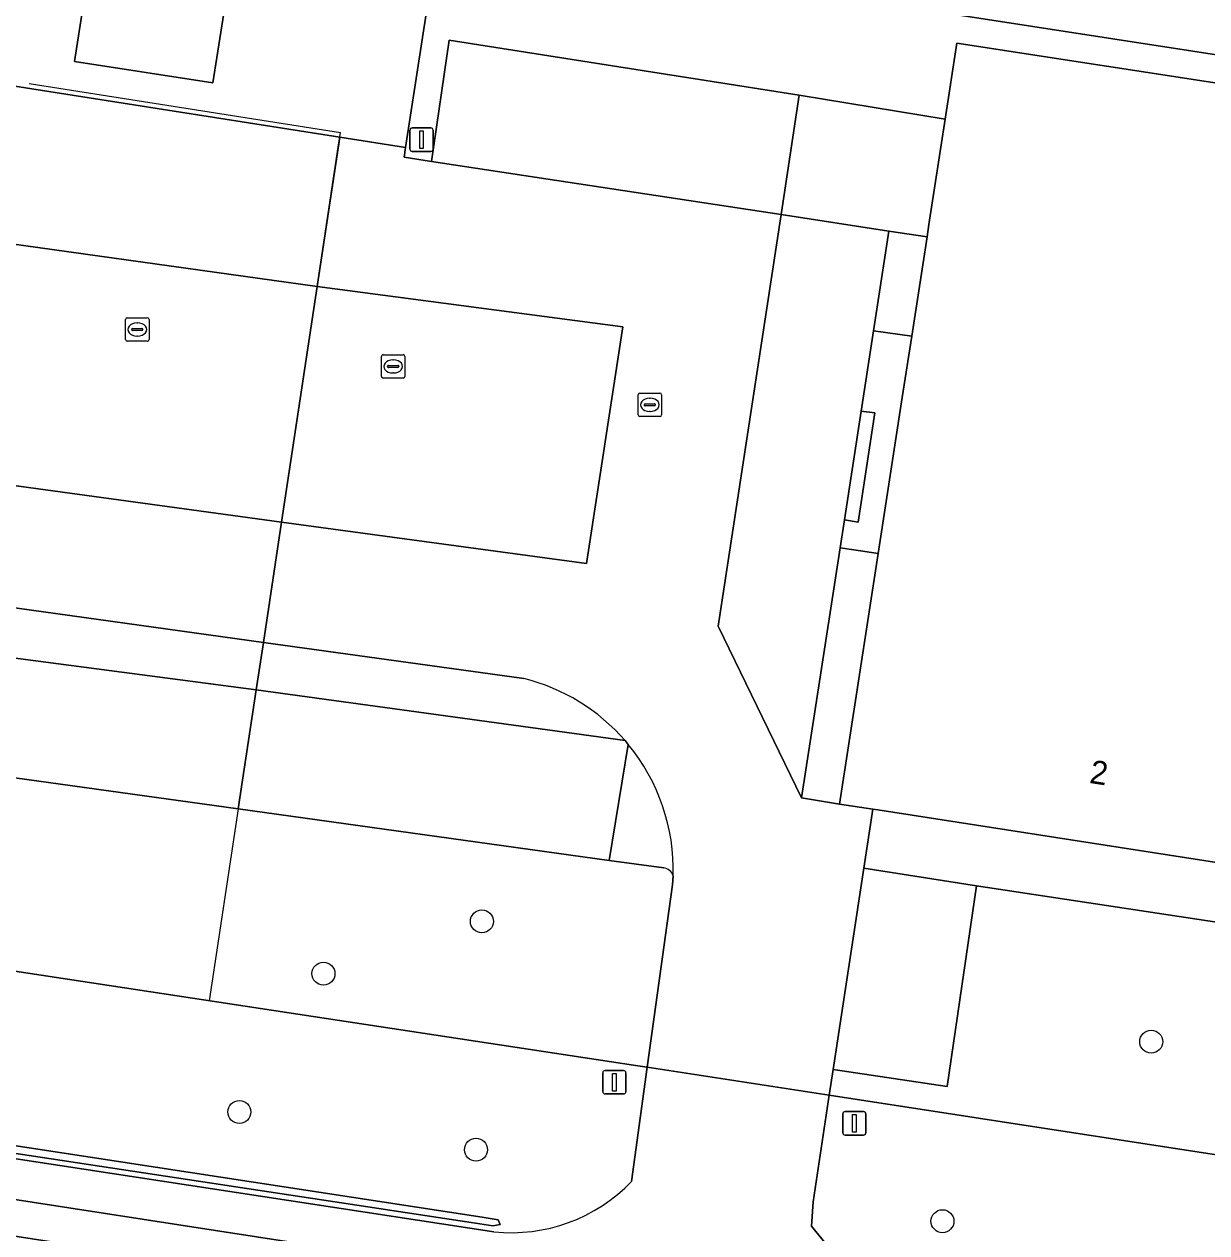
# Model space of a CAD drawing. Extents: x 161090 to 161692, y 379509 to 380907.
# Drawn here: x 161358.3 to 161408.7, y 380170.9 to 380222.4 of the extents above; entities that cross this region are included whole.
import ezdxf

# ---------------------------------------------------------------- set-up
doc = ezdxf.new("R2010")
doc.units = 0
for name, color, linetype in [('IMGEO_Boom', 7, 'Continuous'), ('IMGEO_Erf', 7, 'Continuous'), ('IMGEO_Greppel_droge_sloot', 7, 'Continuous'), ('IMGEO_Groenvoorziening', 7, 'Continuous'), ('IMGEO_Hek', 7, 'Continuous'), ('IMGEO_Kolk', 7, 'Continuous'), ('IMGEO_Lichtmast', 7, 'Continuous'), ('IMGEO_Pand', 7, 'Continuous'), ('IMGEO_Pand_nummerreeks', 7, 'Continuous'), ('IMGEO_Parkeervlak_gesloten', 7, 'Continuous'), ('IMGEO_Parkeervlak_open', 7, 'Continuous'), ('IMGEO_Rijbaan_lokaal_gesloten', 7, 'Continuous'), ('IMGEO_Rijbaan_lokaal_open', 7, 'Continuous'), ('IMGEO_Vlaggenmast', 7, 'Continuous'), ('IMGEO_Voetpad_gesloten', 7, 'Continuous'), ('IMGEO_Voetpad_open', 7, 'Continuous')]:
    doc.layers.add(name, color=color, linetype=linetype)

msp = doc.modelspace()

# ---------------------------------------------------------------- linework, layer by layer
at = {"layer": 'IMGEO_Boom'}
for centre in [(161377.798, 380184.155), (161371.038, 380181.93), (161406.356, 380179.026), (161367.451, 380176.028), (161377.548, 380174.418), (161397.449, 380171.369)]:
    msp.add_circle(centre, 0.489, dxfattribs=at)
at = {"layer": 'IMGEO_Erf'}
msp.add_lwpolyline([(161409.258, 380230.799), (161406.633, 380231.213), (161406.436, 380230.025), (161403.674, 380230.45), (161395.611, 380231.692), (161392.575, 380232.159), (161392.771, 380233.346), (161390.164, 380233.785), (161389.956, 380232.608), (161377.647, 380234.485), (161377.818, 380235.694), (161375.151, 380236.109), (161374.962, 380234.946), (161360.618, 380237.083), (161360.488, 380235.811), (161361.823, 380235.576), (161361.002, 380230.646), (161360.642, 380228.481), (161375.926, 380226.19), (161390.875, 380223.949), (161435.81, 380217.001)], dxfattribs=at)
at = {"layer": 'IMGEO_Greppel_droge_sloot'}
msp.add_lwpolyline([(161343.135, 380176.847), (161342.43, 380176.975), (161342.13, 380176.942), (161341.888, 380176.892), (161342.296, 380176.684), (161343.079, 380176.509), (161377.338, 380171.315), (161378.264, 380171.169), (161378.582, 380171.222), (161378.489, 380171.421), (161377.814, 380171.54)], close=True, dxfattribs=at)
at = {"layer": 'IMGEO_Groenvoorziening'}
for points in [[(161398.066, 380221.612), (161430.36, 380216.65), (161430.062, 380214.725), (161436.256, 380214.823), (161435.81, 380217.001), (161390.875, 380223.949), (161375.926, 380226.19), (161374.541, 380217.165), (161374.478, 380216.751), (161375.644, 380216.573), (161376.403, 380221.743), (161391.337, 380219.395), (161397.566, 380218.371)], [(161397.566, 380218.371), (161391.337, 380219.395), (161390.561, 380214.301), (161395.158, 380213.601), (161396.792, 380213.349), (161396.873, 380213.882)], [(161447.375, 380210.911), (161450.624, 380215.303), (161443.838, 380216.302), (161435.922, 380213.474), (161435.211, 380208.698), (161435.321, 380202.036), (161434.264, 380202.041), (161434.402, 380194.895), (161421.663, 380194.634), (161422.025, 380182.174), (161398.904, 380185.676), (161397.648, 380177.109), (161392.782, 380177.842), (161392.614, 380176.746), (161417.36, 380172.937), (161419.036, 380174.653), (161420.915, 380175.958), (161427.803, 380177.942), (161437.979, 380182.066), (161446.954, 380185.824), (161448.966, 380187.605), (161443.277, 380193.675)], [(161396.792, 380213.349), (161395.158, 380213.601), (161394.505, 380209.351), (161396.139, 380209.118)], [(161394.571, 380205.841), (161393.978, 380205.925), (161393.264, 380201.278), (161393.854, 380201.191)], [(161394.708, 380199.845), (161393.671, 380200.005), (161393.082, 380200.096), (161391.442, 380189.428), (161393.061, 380189.161)], [(161343.135, 380176.847), (161377.814, 380171.54), (161378.489, 380171.421), (161378.582, 380171.222), (161378.264, 380171.169), (161377.338, 380171.315), (161343.079, 380176.509), (161342.296, 380176.684), (161341.888, 380176.892), (161342.13, 380176.942), (161342.43, 380176.975)]]:
    msp.add_lwpolyline(points, close=True, dxfattribs=at)
for points in [[(161367.404, 380188.952), (161345.25, 380192.024), (161343.216, 380192.377), (161342.232, 380184.401), (161384.456, 380178.002), (161384.853, 380177.941), (161385.938, 380185.721), (161385.959, 380186.104)], [(161385.555, 380186.435), (161383.228, 380186.758), (161367.404, 380188.952)], [(161384.853, 380177.941), (161384.456, 380178.002), (161342.232, 380184.401), (161341.266, 380176.581), (161378.314, 380170.916)], [(161384.188, 380173.066), (161384.853, 380177.941)], [(161417.36, 380172.937), (161392.614, 380176.746), (161391.926, 380172.195), (161391.858, 380171.161), (161393.058, 380169.694), (161393.83, 380168.887)]]:
    msp.add_lwpolyline(points, dxfattribs=at)
for centre, radius, start, end in [((161385.52, 380185.98), 0.456, 15.7768, 85.5672), ((161379.05, 380178.004), 7.126, 264.0691, 316.1382)]:
    msp.add_arc(centre, radius, start, end, dxfattribs=at)
at = {"layer": 'IMGEO_Hek'}
for points in [[(161358.487, 380219.889), (161371.767, 380217.811)], [(161371.672, 380217.178), (161371.767, 380217.811)], [(161368.478, 380196.055), (161371.672, 380217.178)], [(161367.404, 380188.952), (161368.478, 380196.055)], [(161367.404, 380188.952), (161366.156, 380180.775)], [(161384.456, 380178.002), (161342.232, 380184.401)], [(161384.456, 380178.002), (161384.853, 380177.941)], [(161384.853, 380177.941), (161392.614, 380176.746)], [(161417.36, 380172.937), (161392.614, 380176.746)]]:
    msp.add_lwpolyline(points, dxfattribs=at)
at = {"layer": 'IMGEO_Kolk'}
for p, q in [((161362.595, 380208.976), (161362.595, 380209.828)), ((161362.67, 380209.902), (161363.522, 380209.902)), ((161363.596, 380209.828), (161363.596, 380208.976)), ((161362.854, 380209.396), (161362.854, 380209.408)), ((161363.292, 380209.359), (161362.894, 380209.359)), ((161362.897, 380209.445), (161363.295, 380209.445)), ((161363.083, 380209.682), (161363.108, 380209.682)), ((161363.338, 380209.408), (161363.338, 380209.396)), ((161363.522, 380208.902), (161362.67, 380208.902)), ((161363.106, 380209.122), (161363.081, 380209.122)), ((161373.512, 380207.402), (161373.512, 380208.254)), ((161373.587, 380208.328), (161374.439, 380208.328)), ((161374.513, 380208.254), (161374.513, 380207.402)), ((161373.771, 380207.822), (161373.771, 380207.834)), ((161374.209, 380207.785), (161373.811, 380207.785)), ((161373.814, 380207.871), (161374.212, 380207.871)), ((161374, 380208.108), (161374.025, 380208.108)), ((161374.255, 380207.834), (161374.255, 380207.822)), ((161374.439, 380207.328), (161373.587, 380207.328)), ((161374.023, 380207.548), (161373.998, 380207.548)), ((161384.54, 380206.688), (161385.392, 380206.688)), ((161384.465, 380205.762), (161384.465, 380206.614)), ((161384.724, 380206.182), (161384.724, 380206.194)), ((161384.767, 380206.231), (161385.165, 380206.231)), ((161384.953, 380206.468), (161384.978, 380206.468)), ((161385.208, 380206.194), (161385.208, 380206.182)), ((161385.466, 380206.614), (161385.466, 380205.762)), ((161385.392, 380205.688), (161384.54, 380205.688)), ((161385.162, 380206.145), (161384.764, 380206.145)), ((161384.976, 380205.908), (161384.951, 380205.908))]:
    msp.add_line(p, q, dxfattribs=at)
for points in [[(161362.595, 380208.976), (161362.595, 380209.828)], [(161362.67, 380209.902), (161363.522, 380209.902)], [(161363.596, 380209.828), (161363.596, 380208.976)], [(161363.522, 380208.902), (161362.67, 380208.902)], [(161373.512, 380207.402), (161373.512, 380208.254)], [(161373.587, 380208.328), (161374.439, 380208.328)], [(161374.513, 380208.254), (161374.513, 380207.402)], [(161374.439, 380207.328), (161373.587, 380207.328)], [(161384.54, 380206.688), (161385.392, 380206.688)], [(161384.465, 380205.762), (161384.465, 380206.614)], [(161385.466, 380206.614), (161385.466, 380205.762)], [(161385.392, 380205.688), (161384.54, 380205.688)]]:
    msp.add_lwpolyline(points, dxfattribs=at)
for centre, radius, start, end in [((161362.672, 380209.826), 0.0765, 91.552, 178.448), ((161362.672, 380209.826), 0.0765, 91.552, 178.448), ((161363.52, 380209.826), 0.0765, 1.552, 88.448), ((161363.52, 380209.826), 0.0765, 1.552, 88.448), ((161362.894, 380209.405), 0.0403, 85.8775, 175.7526), ((161362.891, 380209.395), 0.0366, 178.938, 274.7102), ((161363.295, 380209.402), 0.043, 264.8664, 352.4533), ((161363.299, 380209.407), 0.0386, 1.7309, 96.639), ((161362.672, 380208.978), 0.0765, 181.552, 268.448), ((161362.672, 380208.978), 0.0765, 181.552, 268.448), ((161363.52, 380208.978), 0.0765, 271.552, 358.448), ((161363.52, 380208.978), 0.0765, 271.552, 358.448), ((161373.589, 380208.252), 0.0765, 91.552, 178.448), ((161373.589, 380208.252), 0.0765, 91.552, 178.448), ((161374.437, 380208.252), 0.0765, 1.552, 88.448), ((161374.437, 380208.252), 0.0765, 1.552, 88.448), ((161373.811, 380207.831), 0.0403, 85.8775, 175.7526), ((161373.808, 380207.821), 0.0366, 178.938, 274.7102), ((161374.212, 380207.828), 0.043, 264.8664, 352.4533), ((161374.216, 380207.833), 0.0386, 1.7309, 96.639), ((161373.589, 380207.404), 0.0765, 181.552, 268.448), ((161373.589, 380207.404), 0.0765, 181.552, 268.448), ((161374.437, 380207.404), 0.0765, 271.552, 358.448), ((161374.437, 380207.404), 0.0765, 271.552, 358.448), ((161384.542, 380206.612), 0.0765, 91.552, 178.448), ((161384.542, 380206.612), 0.0765, 91.552, 178.448), ((161385.39, 380206.612), 0.0765, 1.552, 88.448), ((161385.39, 380206.612), 0.0765, 1.552, 88.448), ((161384.764, 380206.191), 0.0403, 85.8775, 175.7526), ((161384.761, 380206.181), 0.0366, 178.938, 274.7102), ((161385.165, 380206.188), 0.043, 264.8664, 352.4533), ((161385.169, 380206.193), 0.0386, 1.7309, 96.639), ((161384.542, 380205.764), 0.0765, 181.552, 268.448), ((161384.542, 380205.764), 0.0765, 181.552, 268.448), ((161385.39, 380205.764), 0.0765, 271.552, 358.448), ((161385.39, 380205.764), 0.0765, 271.552, 358.448)]:
    msp.add_arc(centre, radius, start, end, dxfattribs=at)
for centre, major_axis, ratio, start_param, end_param in [((161363.082, 380209.402), (-0.387, 0.002), 0.722429, 4.712389, 7.853982), ((161363.107, 380209.402), (-0.39, 0.002), 0.717154, 1.570796, 4.712389), ((161373.999, 380207.828), (-0.387, 0.002), 0.722429, 4.712389, 7.853982), ((161374.024, 380207.828), (-0.39, 0.002), 0.717154, 1.570796, 4.712389), ((161384.952, 380206.188), (-0.387, 0.002), 0.722429, 4.712389, 7.853982), ((161384.977, 380206.188), (-0.39, 0.002), 0.717154, 1.570796, 4.712389)]:
    msp.add_ellipse(centre, major_axis=major_axis, ratio=ratio, start_param=start_param, end_param=end_param, dxfattribs=at)
at = {"layer": 'IMGEO_Lichtmast'}
for p, q in [((161374.73, 380217.1), (161374.73, 380217.9)), ((161374.73, 380217.9), (161374.73, 380217.1)), ((161374.83, 380218), (161375.62, 380218)), ((161375.62, 380218), (161374.83, 380218)), ((161375.72, 380217.9), (161375.72, 380217.1)), ((161375.72, 380217.1), (161375.72, 380217.9)), ((161375.62, 380217), (161374.83, 380217)), ((161374.83, 380217), (161375.62, 380217))]:
    msp.add_line(p, q, dxfattribs=at)
msp.add_lwpolyline([(161375.15, 380217.875), (161375.3, 380217.875), (161375.3, 380217.125), (161375.15, 380217.125), (161375.15, 380217.875)], dxfattribs=at)
for centre, start, end in [((161374.83, 380217.9), 90, 180), ((161374.83, 380217.9), 90, 180), ((161375.62, 380217.9), 0, 90), ((161375.62, 380217.9), 360, 90), ((161374.83, 380217.1), 180, 270), ((161374.83, 380217.1), 180, 270), ((161375.62, 380217.1), 270, 0), ((161375.62, 380217.1), 270, 0)]:
    msp.add_arc(centre, 0.1, start, end, dxfattribs=at)
at = {"layer": 'IMGEO_Pand'}
for points in [[(161366.318, 380219.925), (161367.342, 380226.421), (161361.421, 380227.334), (161360.411, 380220.831)], [(161434.118, 380208.706), (161434.113, 380209.066), (161429.373, 380209.013), (161429.441, 380210.722), (161430.062, 380214.725), (161430.36, 380216.65), (161398.066, 380221.612), (161397.566, 380218.371), (161396.873, 380213.882), (161396.792, 380213.349), (161396.139, 380209.118), (161395.734, 380206.496), (161394.708, 380199.845), (161393.061, 380189.161), (161394.485, 380188.941), (161394.698, 380188.908), (161414.092, 380185.905), (161413.711, 380197.559), (161415.884, 380197.601), (161421.589, 380197.688), (161421.663, 380194.634), (161434.402, 380194.895), (161434.264, 380202.041)]]:
    msp.add_lwpolyline(points, close=True, dxfattribs=at)
at = {"layer": 'IMGEO_Parkeervlak_gesloten'}
for points in [[(161390.561, 380214.301), (161375.644, 380216.573), (161374.478, 380216.751), (161374.541, 380217.165), (161371.736, 380217.604), (161370.773, 380211.232), (161383.814, 380209.513), (161382.266, 380199.428), (161369.255, 380201.191), (161368.478, 380196.055), (161379.583, 380194.513)], [(161385.959, 380186.104), (161385.938, 380185.721), (161384.853, 380177.941), (161392.614, 380176.746), (161392.782, 380177.842), (161394.1, 380186.433), (161394.485, 380188.941), (161393.061, 380189.161), (161391.442, 380189.428), (161387.886, 380196.742), (161390.561, 380214.301)], [(161383.909, 380191.866), (161384.044, 380191.707)]]:
    msp.add_lwpolyline(points, dxfattribs=at)
msp.add_lwpolyline([(161370.773, 380211.232), (161355.78, 380213.332), (161354.283, 380203.225), (161369.255, 380201.191)], close=True, dxfattribs=at)
for centre, radius, start, end in [((161377.567, 380186.36), 8.398, 40.9639, 76.1127), ((161377.55, 380186.359), 8.413, 358.266, 39.4729)]:
    msp.add_arc(centre, radius, start, end, dxfattribs=at)
at = {"layer": 'IMGEO_Parkeervlak_open'}
for points in [[(161390.561, 380214.301), (161391.337, 380219.395), (161376.403, 380221.743), (161375.644, 380216.573)], [(161393.978, 380205.925), (161394.505, 380209.351), (161395.158, 380213.601), (161390.561, 380214.301), (161387.886, 380196.742), (161391.442, 380189.428), (161393.082, 380200.096), (161393.264, 380201.278)], [(161370.773, 380211.232), (161369.255, 380201.191), (161382.266, 380199.428), (161383.814, 380209.513)], [(161368.172, 380194.03), (161345.886, 380196.958), (161345.25, 380192.024), (161367.404, 380188.952)], [(161384.044, 380191.707), (161383.909, 380191.866), (161368.172, 380194.03), (161367.404, 380188.952), (161383.228, 380186.758)], [(161394.1, 380186.433), (161392.782, 380177.842), (161397.648, 380177.109), (161398.904, 380185.676)]]:
    msp.add_lwpolyline(points, close=True, dxfattribs=at)
at = {"layer": 'IMGEO_Rijbaan_lokaal_gesloten'}
for points in [[(161371.736, 380217.604), (161355.409, 380220.159), (161355.223, 380218.827), (161350.316, 380219.596), (161349.423, 380214.134), (161349.625, 380214.008), (161351.009, 380212.94), (161351.753, 380212.406)], [(161353.277, 380206.557), (161352.034, 380198.337), (161368.478, 380196.055), (161369.255, 380201.191), (161354.283, 380203.225), (161355.78, 380213.332), (161370.773, 380211.232), (161371.736, 380217.604)], [(161351.753, 380212.406), (161351.009, 380212.94), (161349.625, 380214.008), (161349.423, 380214.134), (161348.349, 380214.29), (161345.886, 380196.958), (161368.172, 380194.03), (161368.478, 380196.055), (161352.034, 380198.337), (161353.277, 380206.557)], [(161379.583, 380194.513), (161368.478, 380196.055), (161368.172, 380194.03), (161383.909, 380191.866)], [(161384.044, 380191.707), (161383.228, 380186.758), (161385.555, 380186.435)], [(161378.314, 380170.916), (161341.266, 380176.581), (161339.411, 380176.865), (161339.233, 380176.893), (161325.572, 380179.06), (161324.072, 380179.541), (161320.891, 380174.795), (161323.138, 380174.385), (161329.938, 380173.17), (161337.287, 380172.056), (161342.454, 380171.274), (161343.323, 380171.142), (161345.123, 380170.869), (161454.384, 380154.139), (161458.187, 380153.607), (161470.254, 380151.634)], [(161393.83, 380168.887), (161393.058, 380169.694), (161391.858, 380171.161), (161391.926, 380172.195), (161392.614, 380176.746), (161384.853, 380177.941), (161384.188, 380173.066)]]:
    msp.add_lwpolyline(points, dxfattribs=at)
msp.add_lwpolyline([(161446.09, 380158.691), (161445.878, 380157.188), (161397.984, 380164.531), (161323.363, 380176.065), (161323.619, 380177.579), (161398.278, 380166.048)], close=True, dxfattribs=at)
for centre, radius, start, end in [((161377.567, 380186.36), 8.398, 40.9639, 76.1127), ((161377.55, 380186.359), 8.413, 358.266, 39.4729), ((161385.52, 380185.98), 0.456, 15.7768, 85.5672), ((161379.05, 380178.004), 7.126, 264.0691, 316.1382)]:
    msp.add_arc(centre, radius, start, end, dxfattribs=at)
at = {"layer": 'IMGEO_Rijbaan_lokaal_open'}
msp.add_lwpolyline([(161323.619, 380177.579), (161323.363, 380176.065), (161397.984, 380164.531), (161445.878, 380157.188), (161446.09, 380158.691), (161398.278, 380166.048)], close=True, dxfattribs=at)
at = {"layer": 'IMGEO_Vlaggenmast'}
for p, q in [((161382.954, 380176.896), (161382.954, 380177.696)), ((161382.954, 380177.696), (161382.954, 380176.896)), ((161383.054, 380177.796), (161383.844, 380177.796)), ((161383.844, 380177.796), (161383.054, 380177.796)), ((161383.944, 380177.696), (161383.944, 380176.896)), ((161383.944, 380176.896), (161383.944, 380177.696)), ((161383.844, 380176.796), (161383.054, 380176.796)), ((161383.054, 380176.796), (161383.844, 380176.796)), ((161393.195, 380175.144), (161393.195, 380175.944)), ((161393.195, 380175.944), (161393.195, 380175.144)), ((161393.295, 380176.044), (161394.085, 380176.044)), ((161394.085, 380176.044), (161393.295, 380176.044)), ((161394.185, 380175.944), (161394.185, 380175.144)), ((161394.185, 380175.144), (161394.185, 380175.944)), ((161394.085, 380175.044), (161393.295, 380175.044)), ((161393.295, 380175.044), (161394.085, 380175.044))]:
    msp.add_line(p, q, dxfattribs=at)
for points in [[(161383.374, 380177.671), (161383.524, 380177.671), (161383.524, 380176.921), (161383.374, 380176.921), (161383.374, 380177.671)], [(161393.615, 380175.919), (161393.765, 380175.919), (161393.765, 380175.169), (161393.615, 380175.169), (161393.615, 380175.919)]]:
    msp.add_lwpolyline(points, dxfattribs=at)
for centre, start, end in [((161383.054, 380177.696), 90, 180), ((161383.054, 380177.696), 90, 180), ((161383.844, 380177.696), 0, 90), ((161383.844, 380177.696), 360, 90), ((161383.054, 380176.896), 180, 270), ((161383.054, 380176.896), 180, 270), ((161383.844, 380176.896), 270, 0), ((161383.844, 380176.896), 270, 0), ((161393.295, 380175.944), 90, 180), ((161393.295, 380175.944), 90, 180), ((161394.085, 380175.944), 0, 90), ((161394.085, 380175.944), 360, 90), ((161393.295, 380175.144), 180, 270), ((161393.295, 380175.144), 180, 270), ((161394.085, 380175.144), 270, 0), ((161394.085, 380175.144), 270, 0)]:
    msp.add_arc(centre, 0.1, start, end, dxfattribs=at)
at = {"layer": 'IMGEO_Voetpad_gesloten'}
for points in [[(161375.926, 380226.19), (161360.642, 380228.481), (161361.002, 380230.646), (161359.914, 380230.809), (161360.113, 380232.322), (161353.715, 380233.306), (161353.652, 380232.88), (161353.871, 380232.7), (161353.573, 380232.343), (161351.862, 380220.712), (161355.409, 380220.159), (161371.736, 380217.604), (161374.541, 380217.165)], [(161366.318, 380219.925), (161360.411, 380220.831), (161361.421, 380227.334), (161367.342, 380226.421)]]:
    msp.add_lwpolyline(points, close=True, dxfattribs=at)
at = {"layer": 'IMGEO_Voetpad_open'}
for points in [[(161395.734, 380206.496), (161396.139, 380209.118), (161394.505, 380209.351), (161393.978, 380205.925), (161394.571, 380205.841), (161393.854, 380201.191), (161393.264, 380201.278), (161393.082, 380200.096), (161393.671, 380200.005), (161394.708, 380199.845)], [(161421.589, 380197.688), (161415.884, 380197.601), (161414.092, 380185.905), (161394.698, 380188.908), (161394.485, 380188.941), (161394.1, 380186.433), (161398.904, 380185.676), (161422.025, 380182.174), (161421.663, 380194.634)]]:
    msp.add_lwpolyline(points, close=True, dxfattribs=at)

# ---------------------------------------------------------------- texts
at = {"layer": 'IMGEO_Pand_nummerreeks'}
msp.add_text('2', height=1, rotation=351.1994, dxfattribs=at).set_placement((161403.687, 380190.066))

doc.saveas('drawing.dxf')
